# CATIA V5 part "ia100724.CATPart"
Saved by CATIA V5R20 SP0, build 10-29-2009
Part number: IA 100724
Revision: ANY
Definition: UNKNOWN
Nomenclature: IA 100724
Source: Unknown
Bounding box of the stored display mesh (mm): x -5.35 to 5.35, y -17 to 0, z -5.35 to 5.35
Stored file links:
  C:\Users\Utente\Desktop\IO LAVORO\3D X SITO CF\CUMSA\3D files IA\IA 100724\ia100724.CATPart
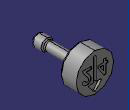
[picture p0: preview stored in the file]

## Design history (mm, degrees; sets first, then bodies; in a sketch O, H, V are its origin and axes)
Body1 "Cortar-Extruir2" (main body)
  Solid1: solid without history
